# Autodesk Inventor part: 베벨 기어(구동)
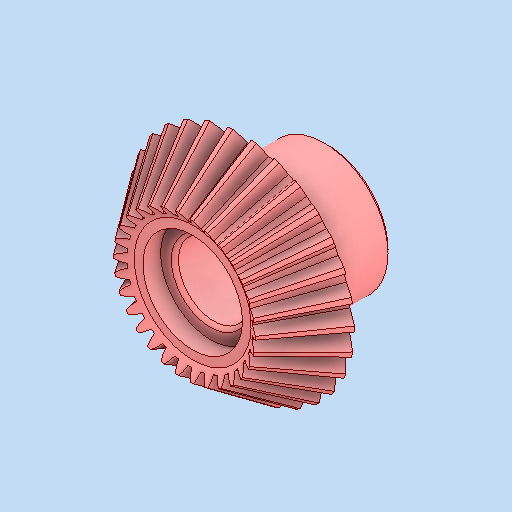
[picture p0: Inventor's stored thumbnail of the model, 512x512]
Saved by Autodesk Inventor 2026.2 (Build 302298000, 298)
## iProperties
Created: 2026-01
Part Number: 베벨 기어(구동)
Material: 강철, 합금
Document SubType Name: Modeling
Designer: PC2-07
Density: 7.73 g/cm^3
Appearance: 기본값
Author: jhkim
Sending System: Autodesk Inventor 2026
Preprocessor: ST-DEVELOPER v20.1
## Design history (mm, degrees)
feature "Solid1"
node "솔리드1"
